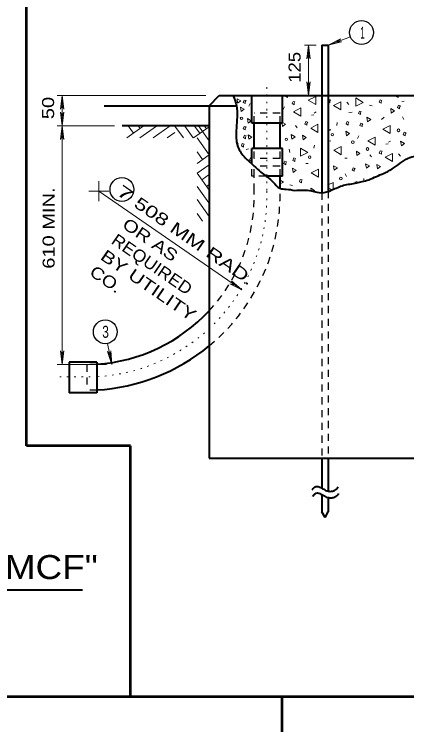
# Model space of a CAD drawing. Extents: x 312583 to 312854, y 144419 to 144597.
# Drawn here: x 312643.98 to 312668.86, y 144504.71 to 144549.76 of the extents above; entities that cross this region are included whole.
import ezdxf
from ezdxf.enums import TextEntityAlignment as Align

# ---------------------------------------------------------------- set-up
doc = ezdxf.new("R2010")
doc.units = 0
doc.header["$LTSCALE"] = 0.3
doc.linetypes.add('DOTTED', pattern=[1.5, 0.3, -1.2])
doc.linetypes.add('SHORT_DASHED', pattern=[2.7, 1.5, -1.2])
doc.layers.add('1', color=7, linetype='Continuous', lineweight=25)
doc.layers.add('2', color=7, linetype='Continuous', lineweight=13)

msp = doc.modelspace()

# ---------------------------------------------------------------- linework, layer by layer
at = {"layer": '1', "lineweight": 53}
for p, q in [((312644.7589, 144522.3988), (312644.7589, 144585.0846)), ((312651.3433, 144522.3988), (312644.7589, 144522.3988)), ((312651.3433, 144506.4889), (312651.3433, 144522.3988)), ((312849, 144506.4889), (312616.5, 144506.4889)), ((312660.9631, 144423.0846), (312660.9631, 144506.4889))]:
    msp.add_line(p, q, dxfattribs=at)
at = {"layer": '1', "lineweight": 40}
for p, q in [((312663.4881, 144547.7893), (312663.8867, 144547.7893)), ((312663.4881, 144547.7893), (312663.4881, 144538.4283)), ((312663.8867, 144547.7893), (312663.8867, 144538.5509)), ((312656.3351, 144543.9559), (312656.9791, 144544.5999)), ((312656.9791, 144544.5999), (312705.5321, 144544.5999)), ((312659.0414, 144542.8443), (312659.0414, 144544.5999)), ((312660.9887, 144542.8443), (312660.9887, 144544.5999)), ((312649.6881, 144543.9559), (312658.0754, 144543.9559)), ((312656.3351, 144543.9559), (312656.3351, 144521.5999)), ((312656.3351, 144543.9559), (312658.0754, 144543.9559)), ((312660.9887, 144542.8443), (312659.0414, 144542.8443)), ((312659.1947, 144541.2419), (312659.1947, 144542.8443)), ((312660.8277, 144541.2419), (312660.8277, 144542.8443)), ((312656.3351, 144542.6833), (312650.8304, 144542.6833)), ((312660.9887, 144541.2419), (312659.0414, 144541.2419)), ((312659.0414, 144540.2759), (312659.0414, 144541.2419)), ((312660.9887, 144539.4863), (312660.9887, 144541.2419)), ((312660.9887, 144539.4863), (312659.9384, 144539.4863)), ((312660.8277, 144538.7119), (312660.8277, 144539.4863)), ((312649.2204, 144527.7026), (312647.4571, 144527.7026)), ((312647.4571, 144527.7026), (312647.4571, 144525.7553)), ((312649.2204, 144527.7026), (312649.2204, 144525.7553)), ((312649.2204, 144525.7553), (312647.4571, 144525.7553)), ((312656.3351, 144521.5999), (312706.1684, 144521.5999)), ((312663.4881, 144521.5999), (312663.4881, 144519.7063)), ((312663.8867, 144521.5999), (312663.8867, 144519.5223)), ((312663.4881, 144519.2999), (312663.4881, 144518.2036)), ((312663.8867, 144519.1159), (312663.8867, 144518.2036)), ((312663.6874, 144517.8586), (312663.4881, 144518.2036)), ((312663.6874, 144517.8586), (312663.8867, 144518.2036))]:
    msp.add_line(p, q, dxfattribs=at)
at = {"layer": '1', "linetype": 'DOTTED', "lineweight": 13}
for p, q in [((312659.9921, 144538.5893), (312659.9921, 144545.3973)), ((312649.2664, 144526.7673), (312646.7517, 144526.7673))]:
    msp.add_line(p, q, dxfattribs=at)
at = {"layer": '1', "linetype": 'SHORT_DASHED'}
for p, q in [((312660.8277, 144543.4806), (312659.1947, 144543.4806)), ((312659.1947, 144542.8443), (312659.1947, 144543.4806)), ((312660.8277, 144542.8443), (312660.8277, 144543.4806)), ((312659.1947, 144540.6056), (312659.1947, 144541.2419)), ((312660.8277, 144540.6056), (312660.8277, 144541.2419)), ((312660.8277, 144540.6056), (312659.1947, 144540.6056)), ((312660.8277, 144540.1226), (312659.1947, 144540.1226)), ((312660.8277, 144539.4863), (312660.8277, 144540.1226)), ((312660.8277, 144537.9146), (312660.8277, 144538.7119)), ((312663.4881, 144538.4283), (312663.4881, 144521.5999)), ((312663.8867, 144538.5509), (312663.8867, 144521.5999)), ((312648.5764, 144527.5416), (312648.5764, 144525.9163)), ((312649.2204, 144527.5416), (312648.5764, 144527.5416)), ((312649.2204, 144525.9163), (312648.5764, 144525.9163))]:
    msp.add_line(p, q, dxfattribs=at)
for points in [[(312659.9384, 144539.4863), (312659.0414, 144539.4863), (312659.0414, 144540.2759)], [(312659.1947, 144538.5663), (312659.1947, 144539.4863), (312659.1947, 144540.1226)]]:
    msp.add_lwpolyline(points, dxfattribs=at)
at = {"layer": '1', "linetype": 'DOTTED', "lineweight": 13}
msp.add_arc((312648.5119, 144538.2296), 11.484, 273.78468, 1.79807, dxfattribs=at)
at = {"layer": '1', "linetype": 'SHORT_DASHED'}
for radius, start, end in [(10.6854, 317.09104, 1.79879), (12.3146, 309.45992, 358.54034)]:
    msp.add_arc((312648.5119, 144538.2296), radius, start, end, dxfattribs=at)
at = {"layer": '1', "lineweight": 40}
for radius, start, end in [(10.6854, 273.78468, 317.09104), (12.3146, 273.28354, 309.45992)]:
    msp.add_arc((312648.5119, 144538.2296), radius, start, end, dxfattribs=at)
for points in [[(312657.8684, 144544.5846), (312658.0754, 144543.9559), (312658.1597, 144541.3493), (312658.6197, 144540.6516), (312659.1257, 144540.1916), (312659.6931, 144539.6856), (312660.3907, 144539.1183), (312660.8201, 144538.7196), (312661.2264, 144538.6659), (312661.7707, 144538.5816)], [(312661.7707, 144538.5816), (312662.8364, 144538.5586), (312663.4651, 144538.4359), (312664.1167, 144538.6123), (312664.8604, 144538.9113), (312665.6884, 144539.0569), (312666.0411, 144539.1489), (312666.4627, 144539.2639), (312666.9381, 144539.4709), (312667.3827, 144539.6549), (312668.4484, 144540.3066), (312668.9544, 144540.6286), (312669.8744, 144540.8433), (312670.5567, 144541.0733), (312671.2927, 144541.4336), (312672.4811, 144542.4149), (312673.1634, 144543.0359), (312674.0221, 144543.9253), (312674.2904, 144544.5999)], [(312662.8671, 144519.5989), (312663.0204, 144519.7676), (312663.1661, 144519.8213), (312663.3194, 144519.7829), (312663.4497, 144519.7063), (312663.6031, 144519.6373), (312663.7181, 144519.5606), (312663.8867, 144519.5223), (312664.0171, 144519.5069), (312664.1474, 144519.5223), (312664.3927, 144519.6373), (312664.5231, 144519.7829)], [(312662.9054, 144519.1849), (312663.0587, 144519.3536), (312663.2044, 144519.4073), (312663.3577, 144519.3689), (312663.4881, 144519.2999), (312663.6414, 144519.2233), (312663.7487, 144519.1466), (312663.9251, 144519.1083), (312664.0554, 144519.0929), (312664.1857, 144519.1083), (312664.4311, 144519.2233), (312664.5614, 144519.3689)]]:
    msp.add_spline(points, degree=3, dxfattribs=at)
at = {"layer": '2'}
for p, q in [((312665.2897, 144548.3259), (312663.8867, 144547.7893)), ((312663.8867, 144547.7893), (312664.6534, 144548.2033)), ((312664.6534, 144548.2033), (312664.4387, 144548.0039)), ((312663.1277, 144547.7893), (312662.3841, 144547.7893)), ((312662.6371, 144547.7893), (312662.5297, 144546.9229)), ((312662.6371, 144544.5999), (312662.6371, 144547.7893)), ((312662.6371, 144547.7893), (312662.7444, 144546.9229)), ((312663.8867, 144547.7893), (312664.7301, 144548.0039)), ((312664.7301, 144548.0039), (312664.4387, 144548.0039)), ((312662.5297, 144546.9229), (312662.6371, 144547.1989)), ((312662.7444, 144546.9229), (312662.6371, 144547.1989)), ((312662.5297, 144545.4663), (312662.6371, 144545.1903)), ((312662.6371, 144544.5999), (312662.5297, 144545.4663)), ((312662.7444, 144545.4663), (312662.6371, 144545.1903)), ((312662.6371, 144544.5999), (312662.7444, 144545.4663)), ((312656.1281, 144544.5999), (312646.6987, 144544.5999)), ((312647.0272, 144544.5999), (312646.9198, 144543.7336)), ((312647.0272, 144544.5999), (312647.1345, 144543.7336)), ((312661.3107, 144544.5769), (312661.3184, 144544.5923)), ((312665.0674, 144544.1859), (312665.1901, 144544.0249)), ((312668.1954, 144544.5463), (312668.3257, 144544.4696)), ((312668.3257, 144544.4696), (312668.3257, 144544.5463)), ((312668.5404, 144544.2319), (312668.6937, 144544.2473)), ((312646.9198, 144543.7336), (312647.0272, 144544.0096)), ((312647.1345, 144543.7336), (312647.0272, 144544.0096)), ((312658.9264, 144544.0939), (312658.8497, 144543.9253)), ((312661.1037, 144543.8793), (312661.0271, 144543.7106)), ((312666.5011, 144543.9943), (312666.6697, 144543.9483)), ((312646.9198, 144543.5496), (312647.0272, 144543.2736)), ((312647.0272, 144542.6833), (312646.9198, 144543.5496)), ((312647.1345, 144543.5496), (312647.0272, 144543.2736)), ((312647.0272, 144542.6833), (312647.1345, 144543.5496)), ((312662.8134, 144543.3503), (312662.9667, 144543.3809)), ((312662.9897, 144543.4883), (312663.1124, 144543.5573)), ((312665.1824, 144543.5266), (312665.3971, 144543.5419)), ((312668.5864, 144543.2583), (312668.6707, 144543.0896)), ((312660.9581, 144542.8366), (312660.9887, 144542.6296)), ((312664.4234, 144542.6986), (312664.4464, 144542.8903)), ((312667.4364, 144543.2199), (312667.2524, 144543.0819)), ((312650.3321, 144542.6833), (312646.6987, 144542.6833)), ((312647.0272, 144542.6833), (312646.9198, 144541.8169)), ((312647.0272, 144542.6833), (312647.1345, 144541.8169)), ((312651.1217, 144541.9166), (312652.2104, 144542.6909)), ((312651.2061, 144542.6833), (312651.5357, 144542.2156)), ((312651.8347, 144542.6833), (312651.9574, 144542.5146)), ((312651.9497, 144541.9166), (312652.9924, 144542.6603)), ((312652.7931, 144541.9166), (312653.8664, 144542.6833)), ((312654.1577, 144542.6679), (312654.7021, 144541.9089)), ((312654.7864, 144542.6679), (312655.3307, 144541.9089)), ((312655.3461, 144541.9166), (312656.3351, 144542.6219)), ((312655.4151, 144542.6679), (312655.7447, 144542.2079)), ((312655.6527, 144542.6833), (312656.3351, 144541.7249)), ((312656.0437, 144542.6679), (312656.1664, 144542.4993)), ((312661.8091, 144542.6986), (312661.9164, 144542.5529)), ((312646.9198, 144541.8169), (312647.0272, 144542.0929)), ((312647.1345, 144541.8169), (312647.0272, 144542.0929)), ((312653.6747, 144541.9166), (312654.1577, 144542.2616)), ((312655.5761, 144541.9089), (312656.3351, 144540.8433)), ((312665.8187, 144542.0393), (312665.7421, 144541.8706)), ((312658.1444, 144541.5716), (312658.1674, 144541.5333)), ((312662.9821, 144541.2726), (312663.0051, 144541.4566)), ((312663.9097, 144541.7173), (312664.0554, 144541.7249)), ((312667.5361, 144541.5103), (312667.6817, 144541.5333)), ((312667.7047, 144541.6406), (312667.8274, 144541.7096)), ((312655.5761, 144541.0273), (312655.9211, 144540.5443)), ((312658.6811, 144541.1729), (312658.8267, 144541.2189)), ((312660.9887, 144540.9966), (312661.0041, 144541.0043)), ((312661.4181, 144541.1959), (312661.4411, 144540.9813)), ((312656.3351, 144540.8433), (312655.5761, 144540.2989)), ((312659.0261, 144540.5366), (312659.0414, 144540.5596)), ((312664.9294, 144540.6209), (312665.0751, 144540.6286)), ((312666.5241, 144540.8509), (312666.6314, 144540.7129)), ((312668.3411, 144540.9123), (312668.4637, 144540.7513)), ((312656.3351, 144540.2146), (312655.5761, 144539.6703)), ((312662.4684, 144540.2913), (312662.6141, 144540.2913)), ((312655.5761, 144539.6703), (312656.3504, 144538.5893)), ((312664.9677, 144539.6396), (312665.0521, 144539.4709)), ((312656.3351, 144539.5859), (312655.8751, 144539.2563)), ((312666.1331, 144539.3483), (312666.1484, 144539.2179)), ((312649.3354, 144538.5279), (312649.3354, 144539.1643)), ((312655.5761, 144538.8423), (312656.3197, 144537.7996)), ((312656.3351, 144538.9573), (312656.1664, 144538.8423)), ((312661.4411, 144538.9419), (312661.6097, 144538.9036)), ((312663.8867, 144538.7503), (312664.0937, 144538.6276)), ((312665.5734, 144539.1183), (312665.7191, 144539.1566)), ((312649.3354, 144538.5279), (312648.7067, 144538.5279)), ((312649.3354, 144538.5279), (312658.4127, 144532.2719)), ((312649.3354, 144538.5279), (312649.3354, 144537.8993)), ((312649.3354, 144538.5279), (312649.9717, 144538.5279)), ((312655.5761, 144537.9989), (312656.3351, 144536.9256)), ((312655.5761, 144537.1173), (312655.9211, 144536.6343)), ((312657.6384, 144532.6706), (312657.9297, 144532.6016)), ((312658.4127, 144532.2719), (312657.6384, 144532.6706)), ((312657.7611, 144532.8469), (312657.9297, 144532.6016)), ((312658.4127, 144532.2719), (312657.7611, 144532.8469)), ((312649.9027, 144528.8833), (312650.1787, 144527.5416)), ((312646.9198, 144528.4079), (312647.0272, 144528.1319)), ((312647.0272, 144527.5416), (312646.9198, 144528.4079)), ((312647.1345, 144528.4079), (312647.0272, 144528.1319)), ((312647.0272, 144527.5416), (312647.1345, 144528.4079)), ((312649.9027, 144528.3696), (312650.0561, 144528.1243)), ((312650.1787, 144527.5416), (312649.9027, 144528.3696)), ((312650.1097, 144528.4156), (312650.0561, 144528.1243)), ((312650.1787, 144527.5416), (312650.1097, 144528.4156)), ((312649.8261, 144527.5416), (312646.6987, 144527.5416))]:
    msp.add_line(p, q, dxfattribs=at)
at = {"layer": '2', "lineweight": 40}
msp.add_line((312619.6192, 144513.2566), (312648.3002, 144513.2566), dxfattribs=at)
at = {"layer": '2'}
for points in [[(312647.0272, 144527.5416), (312647.0272, 144542.6833), (312647.0272, 144544.5999)], [(312661.2034, 144544.5999), (312661.1804, 144544.5463), (312661.3107, 144544.4696), (312661.3107, 144544.5769)], [(312663.9787, 144544.2549), (312664.0247, 144544.3316), (312663.9251, 144544.3699)], [(312663.9251, 144544.1783), (312663.9787, 144544.1476), (312663.9787, 144544.2549)], [(312663.9174, 144543.3656), (312663.9251, 144543.3733), (312663.9174, 144543.3733)], [(312660.9887, 144542.6296), (312661.1804, 144542.7753), (312660.9887, 144542.8979)], [(312663.9097, 144542.3536), (312664.0401, 144542.4226), (312663.9097, 144542.4993)], [(312660.8277, 144541.7633), (312660.8661, 144541.8323), (312660.8277, 144541.8399)], [(312659.0414, 144540.6286), (312658.9571, 144540.6593), (312658.8957, 144540.5059), (312659.0261, 144540.4293), (312659.0261, 144540.5366)], [(312660.8277, 144539.0109), (312661.0424, 144539.1183), (312660.8277, 144539.2409)], [(312664.1934, 144538.6659), (312664.1934, 144539.0799), (312663.8867, 144538.9343)], [(312662.9514, 144538.5356), (312663.0127, 144538.5816), (312662.7827, 144538.7196), (312662.8057, 144538.5586)]]:
    msp.add_lwpolyline(points, dxfattribs=at)
for points in [[(312658.1444, 144544.1093), (312658.3361, 144544.2549), (312658.1061, 144544.3929)], [(312658.6274, 144544.1936), (312658.6734, 144544.2779), (312658.5584, 144544.3086), (312658.4971, 144544.1553), (312658.6274, 144544.0863)], [(312661.7247, 144544.1169), (312661.7707, 144544.2013), (312661.6557, 144544.2319), (312661.5944, 144544.0863), (312661.7247, 144544.0096)], [(312663.0894, 144544.0249), (312663.0894, 144544.5463), (312662.6217, 144544.3086)], [(312664.6841, 144543.6876), (312664.6841, 144544.2013), (312664.2164, 144543.9713)], [(312665.6347, 144544.4466), (312665.6347, 144543.9253), (312666.1024, 144544.1629)], [(312667.2447, 144544.2089), (312667.2907, 144544.2933), (312667.1757, 144544.3316), (312667.1144, 144544.1783), (312667.2447, 144544.1093)], [(312658.3667, 144543.5879), (312658.5584, 144543.7336), (312658.3284, 144543.8716)], [(312662.1464, 144543.2889), (312662.1464, 144543.8103), (312661.6787, 144543.5726)], [(312667.8811, 144543.4806), (312668.0804, 144543.6263), (312667.8427, 144543.7719)], [(312668.4101, 144543.8639), (312668.4561, 144543.9483), (312668.3411, 144543.9789), (312668.2797, 144543.8333), (312668.4101, 144543.7566)], [(312665.9261, 144543.5036), (312665.9797, 144543.5879), (312665.8571, 144543.6186), (312665.8034, 144543.4653), (312665.9261, 144543.3963)], [(312666.3784, 144542.9363), (312666.5777, 144543.0819), (312666.3401, 144543.2276)], [(312658.8114, 144542.8443), (312659.0031, 144542.9899), (312658.7731, 144543.1356)], [(312662.5374, 144542.8289), (312662.5834, 144542.9056), (312662.4684, 144542.9439), (312662.4071, 144542.7906), (312662.5374, 144542.7216)], [(312663.2351, 144542.2616), (312663.2351, 144542.7753), (312662.7751, 144542.5376)], [(312665.1517, 144542.8366), (312665.1977, 144542.9133), (312665.0827, 144542.9516), (312665.0291, 144542.7983), (312665.1517, 144542.7293)], [(312666.0257, 144542.7369), (312666.0717, 144542.8136), (312665.9567, 144542.8519), (312665.8954, 144542.6986), (312666.0257, 144542.6296)], [(312658.6274, 144542.5223), (312658.6734, 144542.6066), (312658.5584, 144542.6449), (312658.4971, 144542.4916), (312658.6274, 144542.4226)], [(312665.0367, 144542.0469), (312665.2284, 144542.2003), (312664.9984, 144542.3383)], [(312667.8044, 144542.1849), (312667.8044, 144542.6986), (312667.3367, 144542.4686)], [(312658.6427, 144541.9626), (312658.6887, 144542.0469), (312658.5737, 144542.0853), (312658.5124, 144541.9319), (312658.6427, 144541.8553)], [(312658.8497, 144541.8246), (312659.0414, 144541.9703), (312658.8037, 144542.1159)], [(312661.5867, 144541.8399), (312661.7784, 144541.9856), (312661.5407, 144542.1236)], [(312662.2921, 144541.7939), (312662.4837, 144541.9396), (312662.2537, 144542.0853)], [(312666.8614, 144541.4489), (312666.8614, 144541.9626), (312666.3937, 144541.7326)], [(312668.7704, 144542.1466), (312668.8164, 144542.2309), (312668.7014, 144542.2693), (312668.6401, 144542.1159), (312668.7704, 144542.0469)], [(312658.5047, 144541.4413), (312658.5584, 144541.5256), (312658.4357, 144541.5563), (312658.3821, 144541.4106), (312658.5047, 144541.3339)], [(312668.5174, 144541.4106), (312668.7091, 144541.5563), (312668.4714, 144541.7019)], [(312662.1311, 144541.2726), (312662.1311, 144540.7589), (312662.5987, 144540.9889)], [(312664.7071, 144540.8509), (312664.7071, 144541.3646), (312664.2471, 144541.1346)], [(312665.7037, 144540.7896), (312665.8954, 144540.9353), (312665.6654, 144541.0733)], [(312667.2524, 144540.9813), (312667.2984, 144541.0656), (312667.1834, 144541.0963), (312667.1221, 144540.9429), (312667.2524, 144540.8739)], [(312661.7707, 144540.5289), (312661.8167, 144540.6056), (312661.7017, 144540.6439), (312661.6404, 144540.4906), (312661.7707, 144540.4216)], [(312667.9577, 144540.4139), (312667.9577, 144540.9276), (312667.4901, 144540.6976)], [(312661.2034, 144540.3219), (312661.2494, 144540.4063), (312661.1344, 144540.4446), (312661.0731, 144540.2913), (312661.2034, 144540.2146)], [(312664.2624, 144539.8619), (312664.4617, 144540.0076), (312664.2241, 144540.1533)], [(312666.3017, 144539.9923), (312666.4934, 144540.1379), (312666.2557, 144540.2759)], [(312667.0071, 144539.9539), (312667.1987, 144540.0996), (312666.9687, 144540.2376)], [(312661.6634, 144539.7163), (312661.8551, 144539.8619), (312661.6174, 144539.9999)], [(312663.2657, 144539.4249), (312663.2657, 144539.9386), (312662.7981, 144539.7009)], [(312665.5351, 144539.9079), (312665.5811, 144539.9846), (312665.4661, 144540.0229), (312665.4047, 144539.8696), (312665.5351, 144539.8006)], [(312662.1847, 144539.1643), (312662.2307, 144539.2486), (312662.1157, 144539.2869), (312662.0544, 144539.1336), (312662.1847, 144539.0646)]]:
    msp.add_lwpolyline(points, close=True, dxfattribs=at)
at = {"layer": '2', "lineweight": 25}
for centre in [(312665.9938, 144548.5975), (312650.8112, 144538.6429), (312649.7551, 144529.6237)]:
    msp.add_circle(centre, 0.7557, dxfattribs=at)
at = {"layer": '2'}
for centre, radius in [((312658.3914, 144543.1569), 0.0784), ((312668.339, 144542.3942), 0.0865), ((312661.2325, 144541.8184), 0.0784), ((312664.1489, 144542.12), 0.0784), ((312665.443, 144541.6488), 0.0865), ((312666.3752, 144541.2124), 0.0865), ((312662.7058, 144540.6914), 0.0784), ((312664.6764, 144539.3334), 0.0865)]:
    msp.add_circle(centre, radius, dxfattribs=at)

# ---------------------------------------------------------------- texts
for s, width, p in [('1', 0.5, (312665.9225, 144548.2082)), ('3', 0.75, (312649.5611, 144529.2408))]:
    msp.add_text(s, height=0.76, dxfattribs=dict(at, width=width)).set_placement(p)
for s, rotation, width, p in [('125 ', 90, 1.15, (312662.132, 144545.4148)), ('50 ', 90, 1.25, (312646.5091, 144543.1019)), ('7', 325, 1.7, (312650.3923, 144538.3728)), ('610 MIN.  ', 90, 1.25, (312646.5429, 144533.6206)), ('508 MM RAD.   ', 325.387, 1.4, (312651.5021, 144537.5975)), ('OR AS', 325.4, 1.25, (312650.7666, 144536.2676)), ('REQUIRED', 325.4, 1.1, (312650.0738, 144535.2633)), ('BY UTILITY', 325.4, 1.3, (312649.381, 144534.2591)), ('CO.', 325.4, 1.2, (312648.6882, 144533.2549))]:
    msp.add_text(s, height=0.76, rotation=rotation, dxfattribs=dict(at, width=width)).set_placement(p)
at = {"layer": '2', "width": 1.15}
msp.add_text('FOUNDATION TYPE "MCF"', height=1.52, dxfattribs=at).set_placement((312634.4901, 144513.9466), align=Align.CENTER)

doc.saveas('drawing.dxf')
